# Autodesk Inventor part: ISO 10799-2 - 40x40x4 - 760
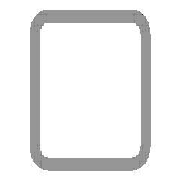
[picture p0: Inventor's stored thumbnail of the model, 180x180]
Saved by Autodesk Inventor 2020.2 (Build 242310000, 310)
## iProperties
Created: 2020-01
Part Number: ISO 10799-2 - 40x40x4 - 760
Material: Steel, Mild
Description: Structural steels - Cold-formed, welded, structural hollow sections
Document SubType Name: Modeling
Standard: ISO
Designer: thira
Standard Revision: First edition 2011-09-15
Standards Organization: ISO
Language: en-US
Size Designation: 40x40x4
Categories: <MemberInstance><Categories><Category DisplayName="Structural Shapes" InternalName="089c4875-fa83-4c05-b084-43b9cc11f5ed" Mnemonic="GRDR"><CategoryParameter Dis
Stock Number: 40x40x4
Density: 7.85 g/cm^3
Appearance: Semi-Polished
_CCFamilyMember: 11
_CCFamilyDisplayName: ISO 10799-2 (Square) - Structural steels - Cold-formed, welded, structural hollow sections
_FrameMemberDoc: Frame Member File
_Version: 15.0.0
_GetPNFromCC: 1
G_L: 760.000 mm
G_W: 40.000 mm
G_H: 40.000 mm
+686CAEAD-CE06-4571-BB35-B6FE03A7DD52+CUTDETAIL1: Cut Angle 90.00 deg
IsCustomPart: 1
Author: thira
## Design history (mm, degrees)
node "Start Plane"
node "End Plane"
sketch "Sketch"
  geometry: L1 (-20, -12)-(-20, 12); L2 (-12, 20)-(12, 20); L3 (20, 12)-(20, -12); L4 (12, -20)-(-12, -20); L5 (-12, 16)-(12, 16); L6 (16, 12)-(16, -12); L7 (12, -16)-(-12, -16); L8 (-16, -12)-(-16, 12); L9 (0, 30.32)-(0, -30.32) reference; L10 (-30.32, 0)-(30.32, 0) reference; A1 r 8 centre (-12, -12) between (-20, -12) and (-12, -20); A2 r 8 centre (12, 12) between (20, 12) and (12, 20); A3 r 8 centre (-12, 12) between (-12, 20) and (-20, 12); A4 r 8 centre (12, -12) between (12, -20) and (20, -12); A5 r 4 centre (-12, 12) between (-12, 16) and (-16, 12); A6 r 4 centre (12, 12) between (16, 12) and (12, 16); A7 r 4 centre (12, -12) between (12, -16) and (16, -12); A8 r 4 centre (-12, -12) between (-16, -12) and (-12, -16)
  constraints: 16 end point, 16 point on circle, 8 centre point, 8 tangent, 4 parallel, 3 equal radius, 2 perpendicular, 7 other
  dimensions: "d7" = 8 radius of A1 (= G_IR); "d9" = 40 distance between parallel lines of L1 L3 (= G_W); "d11" = 40 distance between parallel lines of L2 L4 (= G_H); "d12" = 4 distance between parallel lines of L3 L6 (= G_T); "d15" = 20 distance between parallel lines of L9 L3 (= 0.5 x d9); "d16" = 20 distance between parallel lines of L2 L10 (= 0.5 x d11)
extrude "Body" new body sketch "Sketch" stored distance "d3" = 760 (= G_L); taper "d4" = 0 deg
node "Driven Length"
  sketch "Sketch3"
    geometry: L1 (0, 0)-(10, 0) reference
    constraints: 2 end point, 1 horizontal
  workplane "Work Plane3"
  sketch "Sketch4"
    geometry: L1 (-2, 40)-(12, 40) reference; L2 (-2, 800)-(12, 800) reference
    dimensions: "d18" = 760 distance between parallel lines of L1 L2 (derived)
workplane "Work Plane4"
split "Split1"
body "Solid1"
other parameters: "G_W" = 40 [user parameter; used in 1 equation term], "G_H" = 40 [user parameter; used in 1 equation term], "G_T" = 4 [user parameter; used in 1 equation term], "G_IR" = 8 [user parameter; used in 1 equation term], "G_L" = 760 (= d18) [user parameter; used in 1 equation term], "G_OFFSET_END" = 0 [user parameter; used in 1 equation term], "d17" = 90 deg, "MAS" = 0.42 [user parameter]
